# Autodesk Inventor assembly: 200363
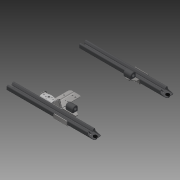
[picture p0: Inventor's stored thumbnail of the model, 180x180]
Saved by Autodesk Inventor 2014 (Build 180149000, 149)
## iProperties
Created: 2007-12
Part Number: 200363
Document SubType Name: Assembly
Designer: MM
Mass: 2378.9 g
Surface Area: 2756.58 cm^2
Volume: 333.729 cm^3
Density: 7.12825 g/cm^3
Description: BOTTOM RAIL ASSEMBLY
Component Category: Lower Component
Author: MM
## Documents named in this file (8)
- C:\Users\iTools\Desktop\tutorial files\Automotive\2000\200363.iam
- C:\Users\iTools\Desktop\tutorial files\Automotive\2000\201169.ipt
- C:\Users\iTools\Desktop\tutorial files\Automotive\2000\200588.ipt
- C:\Users\iTools\Desktop\tutorial files\Automotive\2000\200108.ipt
- C:\Users\iTools\Desktop\tutorial files\Automotive\8000\800168.ipt
- C:\Users\iTools\Desktop\tutorial files\Automotive\2000\200133.ipt
- C:\Users\iTools\Desktop\tutorial files\Automotive\2000\200364.ipt
- C:\Users\iTools\Desktop\tutorial files\Automotive\8000\800987.ipt
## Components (12 placed, 7 different names)
1. 201169:1 — Mate:1, Flush:1, Flush:2, Mate:5, Mate:6, Flush:4, Angle:2, Mate:13, Mate:14, Angle:4
2. 201169:2 — Mate:2, Flush:2, Mate:7, Flush:3, Angle:1, Mate:9, Flush:5, Flush:6, Mate:11, Mate:12, Angle:3
3. 200588:1 — Mate:5, Mate:6, Mate:8, Flush:4, Insert:1, Insert:4
4. 200588:2 — Mate:7, Flush:3, Mate:8, Insert:2, Insert:3
5. 200108:1 — Insert:1, Angle:2
6. 200108:2 — Insert:2, Angle:1
7. 800168:1 — Insert:4
8. 800168:2 — Insert:3
9. 200133:1 — Mate:9, Flush:5, Flush:6, Insert:5, Mate:10
10. 200364:1 — Insert:5, Mate:10
11. 800987:1 — Mate:11, Mate:12, Angle:3
12. 800987:2 — Mate:13, Mate:14, Angle:4
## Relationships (27: Mate 12, Flush 6, Insert 5, Angle 4)
- Mate:1: 201169:1
- Mate:2: 201169:2
- Flush:1: 201169:1
- Flush:2: 201169:1 ↔ 201169:2
- Mate:5: 201169:1 ↔ 200588:1
- Mate:6: 201169:1 ↔ 200588:1
- Mate:7: 201169:2 ↔ 200588:2
- Flush:3: 201169:2 ↔ 200588:2
- Mate:8: 200588:1 ↔ 200588:2
- Flush:4: 201169:1 ↔ 200588:1
- Insert:1: 200588:1 ↔ 200108:1
- Insert:2: 200588:2 ↔ 200108:2
- Angle:1: 201169:2 ↔ 200108:2
- Angle:2: 201169:1 ↔ 200108:1
- Insert:3: 200588:2 ↔ 800168:2
- Insert:4: 200588:1 ↔ 800168:1
- Mate:9: 201169:2 ↔ 200133:1
- Flush:5: 201169:2 ↔ 200133:1
- Flush:6: 201169:2 ↔ 200133:1
- Insert:5: 200133:1 ↔ 200364:1
- Mate:10: 200133:1 ↔ 200364:1
- Mate:11: 201169:2 ↔ 800987:1
- Mate:12: 201169:2 ↔ 800987:1
- Angle:3: 201169:2 ↔ 800987:1
- Mate:13: 201169:1 ↔ 800987:2
- Mate:14: 201169:1 ↔ 800987:2
- Angle:4: 201169:1 ↔ 800987:2
